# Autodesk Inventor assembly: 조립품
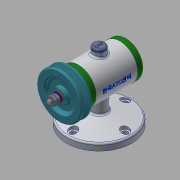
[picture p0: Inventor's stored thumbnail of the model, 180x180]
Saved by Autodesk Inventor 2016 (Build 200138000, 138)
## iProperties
Created: 2018-12
Part Number: 조립품
Material: 일반
Document SubType Name: Assembly
Designer: 605-11
Author: 605-11
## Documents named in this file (15)
- C:\Users\605-11\Desktop\481207V1004\조립품.iam
- C:\Users\605-11\Desktop\481207V1004\본체.ipt
- C:\Users\605-11\Desktop\481207V1004\베어링 15 x 32 x 9.ipt
- C:\Users\605-11\Desktop\481207V1004\축.ipt
- C:\Users\605-11\Desktop\481207V1004\뒤커버.ipt
- C:\Users\605-11\Desktop\481207V1004\볼트 M4 x 12.ipt
- C:\Users\605-11\Desktop\481207V1004\앞커버.ipt
- C:\Users\605-11\Desktop\481207V1004\오일 실 15 25 7.ipt
- C:\Users\605-11\Desktop\481207V1004\키 3 x 3 x 12.ipt
- C:\Users\605-11\Desktop\481207V1004\V벨트풀리.ipt
- C:\Users\605-11\Desktop\481207V1004\와셔 8x17.ipt
- C:\Users\605-11\Desktop\481207V1004\스프링와셔 8.ipt
- C:\Users\605-11\Desktop\481207V1004\너트 M8.ipt
- 너트 M8.ipt
- C:\Users\605-11\Desktop\481207V1004\고무캡.ipt
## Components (2 placed, 2 different names)
1. V벨트풀리:1
2. 고무캡:1 — 플러쉬:3
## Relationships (1: Flush 1)
- 플러쉬:3 [Flush]: 고무캡:1
